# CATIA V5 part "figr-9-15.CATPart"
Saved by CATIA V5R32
Part number: Part1
Bounding box of the stored display mesh (mm): x -77.304 to 77.304, y -77.304 to 118.168, z 0 to 125
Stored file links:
  D:\PROJECTS\Project 2022\CATIA V5 6R 2022\Resources\Part Files\c09_catia_v5_6r2022_prt\c09_catia_v5_6r2022_prt\figr-9-15.CATPart
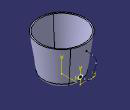
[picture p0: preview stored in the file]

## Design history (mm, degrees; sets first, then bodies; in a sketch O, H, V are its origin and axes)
Set1
  Plane1: type Normal, Curve Sketch3, RefPoint vertex of Sketch3
Body1 (main body)
  Sketch1 on yz-plane, origin (0, 0, 0), H (0, 1, 0), V (0, 0, 1)
    line L1 (0, 0) -> (60, 0)
    point P1 (60, 0)
    point P2 (60, 0)
    line L2 (60, 0) -> (77.5, 125)
    point P3 (77.5, 125)
    line L3 (77.5, 125) -> (0, 125)
    point P4 (0, 125)
    line L4 (0, 125) -> (0, 0)
    axis line L5 (0, 150.2858) -> (0, -31.0593)
    point P5 (0, 150.2858)
    radius about axis P1 L5 = 60
    radius about axis P3 L5 = 77.5
    distance L3 L1 = 125
    horizontal: L1 H, L3 H
    coincidence: P4 V, P2 P1, P5 V
    vertical: L4 V, L5 V
  Shaft1: profile Sketch1, axis Sketch1.L5, angle 360
  Fillet1: radius 15, on edge [face of Shaft1 | face of Shaft1]
  Shell1: ExtOffset 0, Face face of Shaft1, IntOffset 4
  Sketch2 on Plane1, origin (0, 62.9841, 0), H (-1, 0, 0), V (0, 0, 1)
    circle A1 centre (0, 22.002) radius 7.5
    reference projected point E1 (0, 22.002) from vertex of Sketch3
    radius A1 = 7.5
    concentricity: A1 E1
  Sketch3 on yz-plane, origin (0, 0, 0), H (0, 1, 0), V (0, 0, 1)
    line L1 (62.9841, 22.002) -> (78.2172, 22.002)
    arc A1 centre (78.2172, 44.1133) radius 22.1113 from (78.2172, 22.002) to (97.9307, 34.0988) ccw
    arc A2 centre (-112.3295, 140.9107) radius 235.8349 from (97.9307, 34.0988) to (117.8681, 89.6549) ccw
    arc A3 centre (104.0328, 92.7355) radius 14.1742 from (117.8681, 89.6549) to (104.4272, 106.9041) ccw
    arc A4 centre (93.6744, -279.4123) radius 386.4661 from (104.4272, 106.9041) to (82.9216, 106.9041) ccw
    horizontal: L1 H
    tangency: A1 L1, A2 A1, A3 A2, A4 A3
